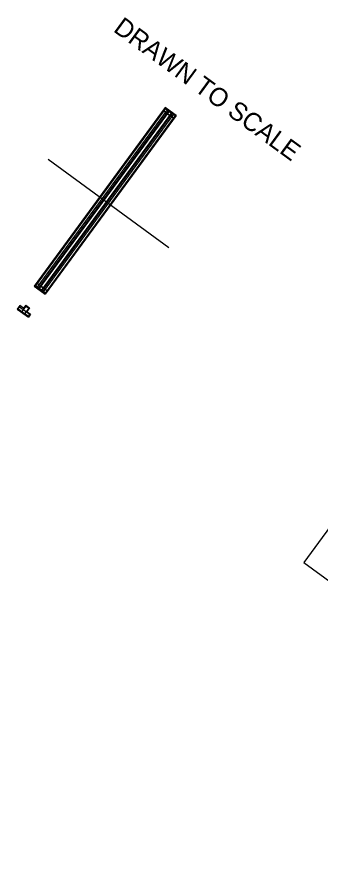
# Model space of a CAD drawing. Extents: x 1970654 to 1970899, y 796145 to 796378.
# Drawn here: x 1970653.6 to 1970735.8, y 796145.2 to 796378.2 of the extents above; entities that cross this region are included whole.
import ezdxf

# ---------------------------------------------------------------- set-up
doc = ezdxf.new("R2010")
doc.units = 0
for name, color, linetype in [('BR_AUTO DIMENSION', 7, 'Continuous'), ('BR_CENTER LINES', 7, 'Continuous'), ('BR_CONCRETE', 7, 'Continuous'), ('BR_REBAR', 7, 'Continuous'), ('Level 31', 7, 'Continuous')]:
    doc.layers.add(name, color=color, linetype=linetype)

msp = doc.modelspace()

# ---------------------------------------------------------------- linework, layer by layer
at = {"layer": 'BR_CENTER LINES'}
msp.add_line((1970661.98, 796339.73), (1970694.7, 796315.77), dxfattribs=at)
at = {"layer": 'BR_CONCRETE'}
for p, q in [((1970693.67, 796353.75), (1970658.18, 796305.27)), ((1970694.68, 796353.01), (1970659.19, 796304.53)), ((1970696.7, 796351.54), (1970693.67, 796353.75)), ((1970695.69, 796352.27), (1970660.2, 796303.79)), ((1970696.7, 796351.54), (1970661.2, 796303.06)), ((1970658.18, 796305.27), (1970661.2, 796303.06)), ((1970654.33, 796300.01), (1970653.59, 796299.01)), ((1970655.34, 796299.28), (1970654.33, 796300.01)), ((1970655.93, 796300.08), (1970655.34, 796299.28)), ((1970655.93, 796300.08), (1970656.94, 796299.34)), ((1970656.94, 796299.34), (1970656.2, 796298.34)), ((1970653.59, 796299.01), (1970656.62, 796296.79)), ((1970656.2, 796298.34), (1970657.21, 796297.6)), ((1970657.21, 796297.6), (1970656.62, 796296.79))]:
    msp.add_line(p, q, dxfattribs=at)
at = {"layer": 'BR_REBAR'}
for p, q in [((1970693.74, 796353.49), (1970658.45, 796305.28)), ((1970694.25, 796353.12), (1970658.95, 796304.91)), ((1970696.42, 796351.43), (1970693.66, 796353.45)), ((1970694.75, 796352.76), (1970659.45, 796304.54)), ((1970695.42, 796352.26), (1970660.13, 796304.05)), ((1970695.93, 796351.89), (1970660.63, 796303.68)), ((1970696.43, 796351.52), (1970661.14, 796303.31)), ((1970695.95, 796350.79), (1970693.19, 796352.81)), ((1970694.91, 796351.49), (1970694.17, 796352.04)), ((1970695.38, 796352.13), (1970694.64, 796352.67)), ((1970661.22, 796303.36), (1970658.46, 796305.38)), ((1970661.69, 796304), (1970658.93, 796306.01)), ((1970660.18, 796304.06), (1970659.44, 796304.6)), ((1970660.65, 796304.7), (1970659.91, 796305.24)), ((1970653.87, 796299.11), (1970654.22, 796299.58)), ((1970656.98, 796297.56), (1970654.22, 796299.58)), ((1970655.97, 796299.85), (1970654.88, 796298.37)), ((1970656.71, 796299.31), (1970655.62, 796297.83)), ((1970655.97, 796299.85), (1970656.71, 796299.31)), ((1970653.87, 796299.11), (1970656.63, 796297.09)), ((1970654.88, 796298.37), (1970655.62, 796297.83)), ((1970656.63, 796297.09), (1970656.98, 796297.56))]:
    msp.add_line(p, q, dxfattribs=at)
for centre in [(1970693.21, 796352.8), (1970693.68, 796353.44), (1970694.19, 796352.02), (1970694.66, 796352.66), (1970694.9, 796351.51), (1970695.36, 796352.15), (1970695.93, 796350.81), (1970696.4, 796351.44), (1970658.48, 796305.36), (1970658.95, 796306), (1970659.46, 796304.59), (1970659.93, 796305.23), (1970660.16, 796304.07), (1970660.63, 796304.71), (1970661.67, 796304.01), (1970661.2, 796303.37)]:
    msp.add_circle(centre, 0.0208, dxfattribs=at)
at = {"layer": 'Level 31'}
for p, q in [((1970693.81, 796353.65), (1970658.31, 796305.17)), ((1970694.82, 796352.91), (1970659.32, 796304.43)), ((1970696.6, 796351.4), (1970693.57, 796353.62)), ((1970695.56, 796352.37), (1970660.06, 796303.89)), ((1970696.56, 796351.63), (1970661.07, 796303.15)), ((1970658.28, 796305.41), (1970661.3, 796303.19))]:
    msp.add_line(p, q, dxfattribs=at)
msp.add_lwpolyline([(1970731.26, 796230.28), (1970847.45, 796145.21), (1970899.43, 796216.22), (1970783.25, 796301.28)], close=True, dxfattribs=at)

# ---------------------------------------------------------------- texts
at = {"layer": 'BR_AUTO DIMENSION'}
msp.add_text('DRAWN TO SCALE', height=5.0012, rotation=323.7906, dxfattribs=at).set_placement((1970679.38, 796374.53))

doc.saveas('drawing.dxf')
